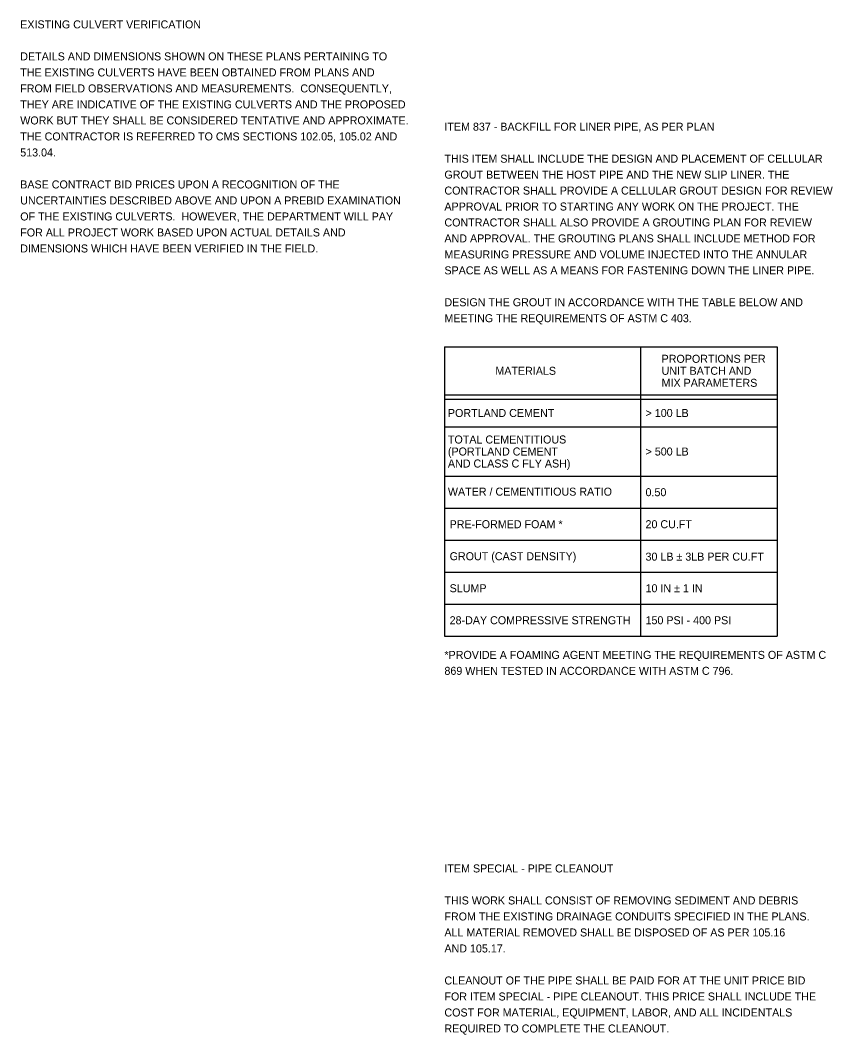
# Model space of a CAD drawing. Extents: x -42.4 to 44.3, y -21.7 to 22.
# Drawn here: x 2.4 to 16.61, y -21.67 to -3.92 of the extents above; entities that cross this region are included whole.
import ezdxf

# ---------------------------------------------------------------- set-up
doc = ezdxf.new("R2010")
doc.units = 0
doc.layers.add('SH_Text', color=7, linetype='Continuous')

msp = doc.modelspace()

# ---------------------------------------------------------------- linework, layer by layer
at = {"layer": 'SH_Text'}
for p, q in [((9.82, -9.634), (15.641, -9.634)), ((9.82, -9.634), (9.82, -14.698)), ((13.25, -9.634), (13.25, -14.698)), ((15.641, -9.634), (15.641, -14.698)), ((9.82, -10.474), (15.641, -10.474)), ((9.82, -10.549), (15.641, -10.549)), ((9.82, -11.034), (15.641, -11.034)), ((9.82, -11.898), (15.641, -11.898)), ((9.82, -11.898), (15.641, -11.898)), ((9.82, -12.458), (15.641, -12.458)), ((9.82, -13.018), (15.641, -13.018)), ((9.82, -13.578), (15.641, -13.578)), ((9.82, -14.138), (15.641, -14.138)), ((9.82, -14.698), (15.641, -14.698))]:
    msp.add_line(p, q, dxfattribs=at)

# ---------------------------------------------------------------- texts
for s, p in [('EXISTING CULVERT VERIFICATION', (2.4, -4.064)), ('DETAILS AND DIMENSIONS SHOWN ON THESE PLANS PERTAINING TO', (2.4, -4.624)), ('THE EXISTING CULVERTS HAVE BEEN OBTAINED FROM PLANS AND', (2.4, -4.904)), ('FROM FIELD OBSERVATIONS AND MEASUREMENTS.  CONSEQUENTLY, ', (2.4, -5.184)), ('THEY ARE INDICATIVE OF THE EXISTING CULVERTS AND THE PROPOSED ', (2.4, -5.464)), ('WORK BUT THEY SHALL BE CONSIDERED TENTATIVE AND APPROXIMATE.  ', (2.4, -5.744)), ('ITEM 837 - BACKFILL FOR LINER PIPE, AS PER PLAN', (9.82, -5.854)), ('THE CONTRACTOR IS REFERRED TO CMS SECTIONS 102.05, 105.02 AND ', (2.4, -6.024)), ('513.04.', (2.4, -6.304)), ('THIS ITEM SHALL INCLUDE THE DESIGN AND PLACEMENT OF CELLULAR ', (9.82, -6.413)), ('GROUT BETWEEN THE HOST PIPE AND THE NEW SLIP LINER. THE ', (9.82, -6.692)), ('BASE CONTRACT BID PRICES UPON A RECOGNITION OF THE ', (2.4, -6.864)), ('CONTRACTOR SHALL PROVIDE A CELLULAR GROUT DESIGN FOR REVIEW ', (9.82, -6.971)), ('UNCERTAINTIES DESCRIBED ABOVE AND UPON A PREBID EXAMINATION ', (2.4, -7.144)), ('APPROVAL PRIOR TO STARTING ANY WORK ON THE PROJECT. THE ', (9.82, -7.25)), ('OF THE EXISTING CULVERTS.  HOWEVER, THE DEPARTMENT WILL PAY', (2.4, -7.424)), ('CONTRACTOR SHALL ALSO PROVIDE A GROUTING PLAN FOR REVIEW', (9.82, -7.529)), ('FOR ALL PROJECT WORK BASED UPON ACTUAL DETAILS AND', (2.4, -7.704)), ('AND APPROVAL. THE GROUTING PLANS SHALL INCLUDE METHOD FOR ', (9.82, -7.808)), ('DIMENSIONS WHICH HAVE BEEN VERIFIED IN THE FIELD.', (2.4, -7.984)), ('MEASURING PRESSURE AND VOLUME INJECTED INTO THE ANNULAR ', (9.82, -8.088)), ('SPACE AS WELL AS A MEANS FOR FASTENING DOWN THE LINER PIPE.', (9.82, -8.367)), ('DESIGN THE GROUT IN ACCORDANCE WITH THE TABLE BELOW AND ', (9.82, -8.925)), ('MEETING THE REQUIREMENTS OF ASTM C 403.', (9.82, -9.204)), ('PROPORTIONS PER', (13.619, -9.914)), ('MATERIALS', (10.711, -10.124)), ('UNIT BATCH AND', (13.619, -10.124)), ('MIX PARAMETERS', (13.619, -10.334)), ('PORTLAND CEMENT', (9.881, -10.862)), ('>', (13.338, -10.862)), (' 100 LB', (13.448, -10.862)), ('TOTAL CEMENTITIOUS', (9.881, -11.326)), ('(PORTLAND CEMENT', (9.881, -11.536)), ('>', (13.338, -11.536)), (' 500 LB', (13.448, -11.536)), ('AND CLASS C FLY ASH)', (9.881, -11.746)), ('WATER / CEMENTITIOUS RATIO', (9.881, -12.238)), ('0.50', (13.338, -12.248)), ('PRE-FORMED FOAM *', (9.911, -12.808)), ('20 CU.FT', (13.338, -12.808)), ('GROUT (CAST DENSITY)', (9.911, -13.368)), ('30 LB ± 3LB PER CU.FT', (13.338, -13.375)), ('SLUMP', (9.911, -13.928)), ('10 IN ± 1 IN', (13.338, -13.928)), ('28-DAY COMPRESSIVE STRENGTH', (9.911, -14.488)), ('150 PSI - 400 PSI', (13.338, -14.488)), ('*PROVIDE A FOAMING AGENT MEETING THE REQUIREMENTS OF ASTM C ', (9.82, -15.094)), ('869 WHEN TESTED IN ACCORDANCE WITH ASTM C 796.', (9.82, -15.373)), ('ITEM SPECIAL - PIPE CLEANOUT', (9.82, -18.83)), ('THIS WORK SHALL CONSIST OF REMOVING SEDIMENT AND DEBRIS', (9.82, -19.39)), ('FROM THE EXISTING DRAINAGE CONDUITS SPECIFIED IN THE PLANS.', (9.82, -19.67)), ('ALL MATERIAL REMOVED SHALL BE DISPOSED OF AS PER 105.16', (9.82, -19.95)), ('AND 105.17.', (9.82, -20.23)), ('CLEANOUT OF THE PIPE SHALL BE PAID FOR AT THE UNIT PRICE BID', (9.82, -20.79)), ('FOR ITEM SPECIAL - PIPE CLEANOUT. THIS PRICE SHALL INCLUDE THE ', (9.82, -21.07)), ('COST FOR MATERIAL, EQUIPMENT, LABOR, AND ALL INCIDENTALS ', (9.82, -21.35)), ('REQUIRED TO COMPLETE THE CLEANOUT.', (9.82, -21.63))]:
    msp.add_text(s, height=0.14, dxfattribs=at).set_placement(p)

doc.saveas('drawing.dxf')
